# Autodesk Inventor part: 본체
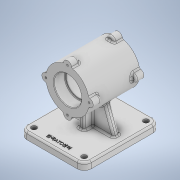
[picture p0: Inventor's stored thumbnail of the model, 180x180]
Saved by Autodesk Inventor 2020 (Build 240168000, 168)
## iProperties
Created: 2022-11
Part Number: 본체
Material: 일반
Document SubType Name: Modeling
Designer: owner
Density: 1 g/cm^3
Appearance: 기본값
Mass: 450.106 g
Surface Area: 797.121 cm^2
Volume: 450.106 cm^3
Author: owner
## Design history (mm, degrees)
sketch "스케치1"
  geometry: L1 (-55, 65)-(55, 65); L2 (55, 65)-(55, -65); L3 (55, -65)-(-55, -65); L4 (-55, -65)-(-55, 65); L5 (-55, 65)-(55, -65); L6 (55, 65)-(-55, -65); 1 further point
  constraints: 12 end point, 2 midpoint, 2 parallel, 1 horizontal, 1 perpendicular
  dimensions: "d0" = 110 distance of L1.start L1.end; "d1" = 130 distance of L3.end L1.start
extrude "돌출1" new body sketch "스케치1" distance "d2" = 12; taper "d3" = 0 deg
node "작업 평면1"
sketch "스케치2"
  geometry: L1 (0, 0)-(110, 0) reference; C1 r 37 at (55, 82); 2 further points
  constraints: 1 centre point, 1 midpoint, 1 vertical alignment
  dimensions: "d5" = 74 diameter of C1; "d44" = 82 distance from line of L1 C1.centre
extrude "돌출2" join sketch "스케치2" stored distance "d6" = 87; taper "d7" = 0 deg
sketch "스케치3"
  geometry: C1 r 37 at (0, 0) reference; 2 further points
  constraints: 1 coincident
hole "구멍1" sketch "스케치3" at (0, 0) diameter "d8" = 42; stored, may be unused: countersink angle "d12" = 90 deg, drill point angle "d14" = 0 deg; dims "d9" = 12, "d10" = 14, "d11" = 4, "d13" = 17.1
sketch "스케치4"
  geometry: C1 r 21 at (0, 0) reference; 2 further points
  constraints: 1 coincident
hole "구멍2" sketch "스케치4" at (0, 0) diameter "d15" = 47; stored, may be unused: countersink angle "d19" = 90 deg, drill point angle "d21" = 0 deg; dims "d16" = 12, "d17" = 14, "d18" = 4, "d20" = 19
sketch "스케치5"
  geometry: C1 r 21 at (0, 0) reference; 2 further points
  constraints: 1 coincident
hole "구멍3" sketch "스케치5" at (0, 0) diameter "d22" = 47; stored, may be unused: countersink angle "d26" = 90 deg, drill point angle "d28" = 0 deg; dims "d23" = 12, "d24" = 14, "d25" = 4, "d27" = 19
sketch "스케치6"
  geometry: C1 r 7 at (0, 37); 3 further points
  constraints: 3 vertical alignment, 1 centre point, 2 other
  dimensions: "d29" = 14 diameter of C1
extrude "돌출3" join sketch "스케치6" distance "d30" = 14; taper "d31" = 0 deg
sketch "스케치7"
  geometry: A1 r 37 centre (55, 82) between (48.031, 118.338) and (61.969, 118.338) reference; A2 r 7 centre (55, 119) between (61.969, 118.338) and (48.031, 118.338) reference; A3 r 37 centre (55, 82) between (61.969, 118.338) and (48.031, 118.338) reference; 2 further points
  constraints: 1 coincident
hole "구멍4" sketch "스케치7" at (55, 119) diameter "d32" = 3.242; stored, may be unused: countersink angle "d36" = 90 deg, drill point angle "d38" = 118 deg; dims "d33" = 8, "d34" = 14, "d35" = 4, "d37" = 10
fillet "모깎기1" dims "d39" = 3
fillet "모깎기2" dims "d40" = 3
node "작업 평면2"
sketch "스케치10"
  geometry: L1 (29.664, 55.036)-(14, 12); L2 (80.336, 55.036)-(96, 12); L3 (0, 12)-(110, 12) reference; L4 (0, 0)-(0, 12) reference; L5 (29.664, 55.036)-(80.336, 55.036); C1 r 1.621 at (92, 82) reference; C2 r 1.621 at (55, 45) reference; C3 r 1.621 at (18, 82) reference; C4 r 1.621 at (55, 119) reference; C5 r 23.5 at (55, 82) reference; A1 r 37 centre (55, 82) between (90.862, 91.104) and (64.104, 117.863) reference; A2 r 3 centre (64.842, 120.77) between (61.889, 120.239) and (64.104, 117.863) reference; A3 r 7 centre (55, 119) between (61.889, 120.239) and (48.111, 120.239) reference; A4 r 3 centre (45.158, 120.77) between (45.896, 117.863) and (48.111, 120.239) reference; A5 r 37 centre (55, 82) between (45.896, 117.863) and (19.137, 91.104) reference; A6 r 3 centre (16.23, 91.842) between (16.761, 88.889) and (19.137, 91.104) reference; A7 r 7 centre (18, 82) between (16.761, 88.889) and (16.761, 75.111) reference; A8 r 3 centre (16.23, 72.158) between (19.137, 72.896) and (16.761, 75.111) reference; A9 r 37 centre (55, 82) between (19.137, 72.896) and (45.896, 46.138) reference; A10 r 3 centre (45.158, 43.23) between (48.111, 43.761) and (45.896, 46.138) reference; A11 r 7 centre (55, 45) between (48.111, 43.761) and (61.889, 43.761) reference; A12 r 3 centre (64.842, 43.23) between (64.104, 46.138) and (61.889, 43.761) reference; A13 r 37 centre (55, 82) between (64.104, 46.138) and (90.862, 72.896) reference; A14 r 3 centre (93.77, 72.158) between (93.239, 75.111) and (90.862, 72.896) reference; A15 r 7 centre (92, 82) between (93.239, 75.111) and (93.239, 88.889) reference; A16 r 3 centre (93.77, 91.842) between (90.862, 91.104) and (93.239, 88.889) reference; A17 r 37 centre (55, 82) between (19.137, 72.896) and (45.896, 46.138) reference; A18 r 37 centre (55, 82) between (64.104, 46.138) and (90.862, 72.896) reference; A19 r 37 centre (55, 82) between (90.862, 91.104) and (64.104, 117.863) reference; A20 r 37 centre (55, 82) between (57.543, 118.913) and (52.457, 118.913) reference; A21 r 37 centre (55, 82) between (45.896, 117.863) and (19.137, 91.104) reference; A22 r 37 centre (55, 82) between (18.087, 84.543) and (18.087, 79.457) reference; A23 r 37 centre (55, 82) between (19.137, 72.896) and (45.896, 46.138) reference; A24 r 37 centre (55, 82) between (52.457, 45.088) and (57.543, 45.088) reference; A25 r 37 centre (55, 82) between (64.104, 46.138) and (90.862, 72.896) reference; A26 r 37 centre (55, 82) between (91.912, 79.457) and (91.912, 84.543) reference; A27 r 37 centre (55, 82) between (64.104, 46.138) and (90.862, 72.896) reference; A28 r 37 centre (55, 82) between (52.457, 45.088) and (57.543, 45.088) reference; A29 r 37 centre (55, 82) between (19.137, 72.896) and (45.896, 46.138) reference; A30 r 37 centre (55, 82) between (18.087, 84.543) and (18.087, 79.457) reference; A31 r 37 centre (55, 82) between (45.896, 117.863) and (19.137, 91.104) reference; A32 r 37 centre (55, 82) between (57.543, 118.913) and (52.457, 118.913) reference; A33 r 37 centre (55, 82) between (90.862, 91.104) and (64.104, 117.863) reference; A34 r 37 centre (55, 82) between (91.912, 79.457) and (91.912, 84.543) reference; 23 further points
  constraints: 6 end point, 2 point on circle, 2 point on line, 16 other
  dimensions: "d47" = 110 deg angle of L3 L1; "d48" = 110 deg angle of L3 L2; "d49" = 14 distance of L3.end L2.end; "d50" = 14 distance from line of L1.end L4
extrude "돌출4" join sketch "스케치10" stored distance "d51" = 10; taper "d52" = 0 deg
sketch "스케치11"
  geometry: L1 (45, -31.5)-(45, 21.5) reference; L2 (45, 15)-(12, 15); L3 (12, -65)-(12, 65) reference; L4 (45, -25)-(12, -25); L5 (12, -25)-(12, 15); L6 (12, 0)-(12, -10) reference; L7 (55.036, 0)-(12, 0) reference; L8 (55.036, -10)-(55.036, 0) reference; L9 (12, -10)-(55.036, -10) reference; L10 (12, 0)-(12, -10) reference; 4 further points
  constraints: 6 end point, 5 midpoint, 4 point on line, 1 coincident, 1 collinear, 1 horizontal, 1 perpendicular
  dimensions: "d53" = 40 distance between parallel lines of L4 L2
feature "리브1" sketch "스케치11" dims "d54" = 1, "d55" = 10, "d56" = 0, "d57" = 0, "d58" = 1, "d59" = 1
fillet "모깎기3" dims "d60" = 12
fillet "모깎기4" dims "d61" = 3
sketch "스케치12"
  geometry: A1 r 9 centre (-43, -53) between (-52, -53) and (-43, -62) reference; 2 further points
  constraints: 1 coincident
hole "구멍5" sketch "스케치12" at (-43, -53) diameter "d62" = 9; stored, may be unused: countersink angle "d66" = 90 deg, drill point angle "d68" = 0 deg; dims "d63" = 8, "d64" = 14, "d65" = 4, "d67" = 10
sketch "스케치13"
  geometry: L1 (43, -62)-(-43, -62) reference; L2 (41, 10)-(41, 0) reference; 4 further points
  constraints: 1 midpoint, 1 vertical alignment, 1 other
  dimensions: "d69" = 58 vertical distance of point (0, -52.949) point (77.365, 5.051)
feature "엠보싱1" sketch "스케치13" dims "d0" = 110, "d1" = 130, "d70" = 0.5, "d71" = 0
chamfer "모따기1" distance "d72" = 1; stored, may be unused: second distance "d73" = 2, angle "d74" = 45 deg
fillet "모깎기5" dims "d75" = 1
fillet "모깎기8" dims "d78" = 3
fillet "모깎기9" dims "d79" = 3
node "솔리드1"
pattern_circular "원형 패턴1" dims "d42" = 360 deg
mirror "미러1"
mirror "미러2"
mirror "미러3"
node "투영된 루프1"
node "투영된 루프2"
node "투영된 루프3"
feature "A9D066F2-1C7D-4E18-AEED-F7BC21143FA4" dims "d8" = 42, "d9" = 12, "d10" = 14, "d11" = 4, "d12" = 90 deg, "d13" = 17.1, "d14" = 0
